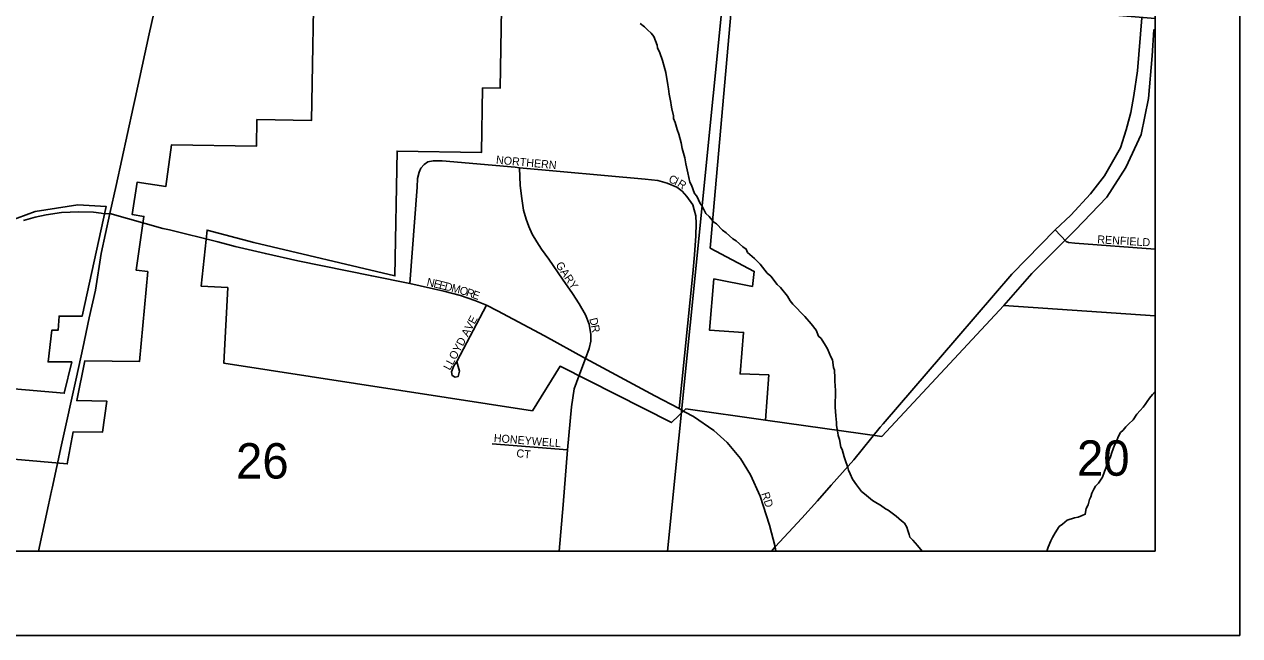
# Model space of a CAD drawing. Extents: x 8.5 to 81.5, y -1.2 to 22.4.
# Drawn here: x 54.915 to 56.353, y 14.351 to 15.074 of the extents above; entities that cross this region are included whole.
import ezdxf

# ---------------------------------------------------------------- set-up
doc = ezdxf.new("R2010")
doc.units = 0
for name, color, linetype in [('GM_X_City_Street', 7, 'Continuous'), ('GM_X_City_Street_Text', 7, 'Continuous'), ('GM_X_Corporation', 7, 'Continuous'), ('GM_X_County', 7, 'Continuous'), ('GM_X_Minor_River', 7, 'Continuous'), ('GM_X_Section', 7, 'Continuous'), ('GM_X_Section_Text', 7, 'Continuous'), ('GM_X_State_Route', 7, 'Continuous'), ('SH_Data', 7, 'Continuous')]:
    doc.layers.add(name, color=color, linetype=linetype)

msp = doc.modelspace()

# ---------------------------------------------------------------- linework, layer by layer
at = {"layer": 'GM_X_City_Street'}
for points in [[(55.3709, 14.767), (55.3793, 14.8811), (55.38, 14.8914), (55.3817, 14.8989), (55.3838, 14.9034), (55.3877, 14.9079), (55.3923, 14.9108), (55.3985, 14.9121), (55.4091, 14.9122), (55.4955, 14.9045), (55.5005, 14.904), (55.6493, 14.8906), (55.6641, 14.889), (55.6754, 14.8857), (55.6867, 14.8812), (55.693, 14.8764), (55.6985, 14.8698), (55.7056, 14.8603), (55.7072, 14.8544), (55.7092, 14.8471), (55.7097, 14.8379), (55.7093, 14.8235), (55.7075, 14.8011), (55.7057, 14.7791), (55.6894, 14.6192)], [(55.5786, 14.6784), (55.5831, 14.6901), (55.5848, 14.6988), (55.5851, 14.7068), (55.583, 14.7188), (55.5785, 14.7302), (55.5713, 14.743), (55.5633, 14.7554), (55.5513, 14.7724), (55.5353, 14.7957), (55.5265, 14.8077), (55.521, 14.8163), (55.5156, 14.8256), (55.5117, 14.8344), (55.5085, 14.8432), (55.5054, 14.854), (55.5032, 14.8677), (55.5013, 14.883), (55.5005, 14.904)], [(55.0057, 14.8501), (54.9965, 14.8513), (54.979, 14.8517), (54.9588, 14.8509), (54.9404, 14.8482), (54.9275, 14.8454), (54.9136, 14.8417)], [(55.0157, 14.85), (55.0092, 14.8496), (55.0057, 14.8501)], [(55.0827, 14.8312), (55.0784, 14.8322), (55.0157, 14.85)], [(55.16, 14.812), (55.1437, 14.8162), (55.0866, 14.8304), (55.0827, 14.8312)], [(56.1344, 14.8304), (56.1474, 14.8169), (56.15, 14.8156), (56.1575, 14.8148), (56.2527, 14.8078)], [(55.6967, 14.6151), (55.6894, 14.6192), (55.6608, 14.6343), (55.594, 14.6702), (55.5786, 14.6784), (55.5302, 14.705), (55.4747, 14.7348), (55.4614, 14.7413), (55.4476, 14.747), (55.4307, 14.7529), (55.4112, 14.7581), (55.3709, 14.767), (55.3257, 14.776), (55.2382, 14.7939), (55.1999, 14.8024), (55.164, 14.811), (55.16, 14.812)], [(55.4614, 14.7413), (55.4263, 14.6748), (55.4229, 14.6696), (55.42, 14.6628), (55.4211, 14.6582), (55.4244, 14.6562), (55.4282, 14.6572), (55.4296, 14.6633), (55.4265, 14.6744)], [(55.5477, 14.4506), (55.5524, 14.5052), (55.5574, 14.5702), (55.5621, 14.6213), (55.5653, 14.6426), (55.5706, 14.6574), (55.5786, 14.6784)], [(55.8032, 14.4558), (55.7965, 14.4813), (55.7854, 14.5156), (55.7739, 14.5406), (55.7621, 14.56), (55.7463, 14.5791), (55.7305, 14.5931), (55.7065, 14.6097), (55.6967, 14.6151)], [(55.4683, 14.5775), (55.5574, 14.5702)], [(55.8038, 14.4506), (55.8032, 14.4558)]]:
    msp.add_lwpolyline(points, dxfattribs=at)
at = {"layer": 'GM_X_Corporation'}
for p, q in [((56.2527, 15.0671), (56.2527, 20.1104)), ((56.2527, 14.729), (56.2527, 15.0671))]:
    msp.add_line(p, q, dxfattribs=at)
for points in [[(54.5101, 15.2197), (55.2579, 15.1582), (55.4802, 15.1396), (55.7533, 15.117), (55.7263, 14.809), (55.7784, 14.7813), (55.7762, 14.7636), (55.7306, 14.7725), (55.7253, 14.712), (55.7658, 14.7092), (55.7615, 14.6601), (55.7955, 14.6589), (55.7918, 14.6056), (55.9292, 14.5863), (56.0735, 14.7412), (56.1067, 14.7788), (56.1582, 14.8303), (56.1954, 14.8691), (56.2181, 14.9044), (56.236, 14.9433), (56.2448, 14.986), (56.2493, 15.0365), (56.2512, 15.0672), (56.2527, 15.0671)], [(54.5101, 15.2197), (55.2579, 15.1582), (55.2544, 14.9598), (55.1899, 14.961), (55.1893, 14.9295), (55.089, 14.9312), (55.082, 14.8818), (55.0482, 14.8871), (55.0422, 14.8488), (55.0562, 14.8465), (55.0472, 14.7827), (55.0607, 14.7811), (55.0508, 14.6747), (54.9864, 14.6758), (54.9768, 14.6286), (55.0123, 14.628), (55.0072, 14.5913), (54.9724, 14.5916), (54.9654, 14.5538), (54.8296, 14.5657)], [(55.2579, 15.1582), (55.2544, 14.9598), (55.1899, 14.961), (55.1893, 14.9295), (55.089, 14.9312), (55.082, 14.8818), (55.0482, 14.8871), (55.0422, 14.8488), (55.0562, 14.8465), (55.0472, 14.7827), (55.0607, 14.7811), (55.0508, 14.6747), (54.9864, 14.6758), (54.9768, 14.6286), (55.0123, 14.628), (55.0072, 14.5913), (54.9724, 14.5916), (54.9654, 14.5538), (54.8296, 14.5657)], [(56.2527, 14.729), (56.0735, 14.7412), (55.9292, 14.5863), (55.7918, 14.6056), (55.6975, 14.6188), (55.6804, 14.6025), (55.5486, 14.6693), (55.5158, 14.6166), (55.1507, 14.673), (55.1554, 14.7623), (55.124, 14.7639), (55.131, 14.8303), (55.1864, 14.8154), (55.3531, 14.776), (55.3557, 14.9238), (55.4555, 14.922), (55.4568, 14.9984), (55.4777, 14.998), (55.4802, 15.1396)], [(55.7533, 15.117), (55.7263, 14.809), (55.7784, 14.7813), (55.7762, 14.7636), (55.7306, 14.7725), (55.7253, 14.712), (55.7658, 14.7092), (55.7615, 14.6601), (55.7955, 14.6589), (55.7918, 14.6056), (55.6975, 14.6188), (55.6804, 14.6025), (55.5486, 14.6693), (55.5158, 14.6166), (55.1507, 14.673), (55.1554, 14.7623), (55.124, 14.7639), (55.131, 14.8303), (55.1864, 14.8154), (55.3531, 14.776), (55.3557, 14.9238), (55.4555, 14.922), (55.4568, 14.9984), (55.4777, 14.998), (55.4802, 15.1396)], [(56.2527, 15.0671), (56.2512, 15.0672), (56.2493, 15.0365), (56.2448, 14.986), (56.236, 14.9433), (56.2181, 14.9044), (56.1954, 14.8691), (56.1582, 14.8303), (56.1067, 14.7788), (56.0735, 14.7412), (56.2527, 14.729)], [(54.8469, 14.6473), (54.962, 14.6372), (54.9707, 14.6743), (54.9428, 14.6743), (54.9474, 14.712), (54.9549, 14.712), (54.9558, 14.7285), (54.9833, 14.7285), (55.0117, 14.858), (54.9779, 14.86), (54.9276, 14.8522), (54.8846, 14.8366)], [(54.8469, 14.6473), (54.962, 14.6372), (54.9707, 14.6743), (54.9428, 14.6743), (54.9474, 14.712), (54.9549, 14.712), (54.9558, 14.7285), (54.9833, 14.7285), (55.0117, 14.858), (54.9779, 14.86), (54.9276, 14.8522), (54.8846, 14.8366)], [(53.1988, 14.4506), (56.2527, 14.4506), (56.2527, 14.729)]]:
    msp.add_lwpolyline(points, dxfattribs=at)
at = {"layer": 'GM_X_County'}
msp.add_lwpolyline([(54.0879, 21.2506), (49.4527, 21.2506), (49.4527, 14.4506), (56.2527, 14.4506), (56.2527, 19.1108)], dxfattribs=at)
at = {"layer": 'GM_X_Minor_River'}
for points in [[(55.7301, 14.8401), (55.7249, 14.8463), (55.7212, 14.8498), (55.7168, 14.8586), (55.7143, 14.8617), (55.7103, 14.8702), (55.7077, 14.8736), (55.7041, 14.8832), (55.7023, 14.8871), (55.6998, 14.8981), (55.6974, 14.9085), (55.6964, 14.9157), (55.6932, 14.9268), (55.6918, 14.9333), (55.689, 14.9436), (55.6872, 14.9494), (55.6847, 14.9574), (55.6829, 14.9624), (55.6826, 14.9654), (55.6809, 14.9735), (55.6799, 14.978), (55.6795, 14.9811), (55.6775, 14.991), (55.6768, 14.9975), (55.6762, 15.0021), (55.6738, 15.0166), (55.6696, 15.0308), (55.6667, 15.0399), (55.6638, 15.0457), (55.6635, 15.0491), (55.6595, 15.0591), (55.6562, 15.063), (55.6521, 15.0672), (55.6484, 15.0707), (55.6435, 15.0746)], [(55.977, 14.4506), (55.9715, 14.4573), (55.9659, 14.4635), (55.9626, 14.467), (55.9615, 14.4701), (55.9601, 14.4751), (55.9587, 14.4789), (55.9561, 14.4835), (55.9527, 14.4863), (55.9464, 14.4921), (55.9367, 14.4992), (55.9337, 14.5007), (55.9277, 14.505), (55.924, 14.507), (55.9183, 14.5106), (55.9086, 14.5184), (55.9053, 14.5211), (55.8994, 14.5288), (55.8946, 14.5358), (55.892, 14.5419), (55.8899, 14.5465), (55.8892, 14.5496), (55.8859, 14.5584), (55.8849, 14.5619), (55.8824, 14.5707), (55.8809, 14.5737), (55.8792, 14.5825), (55.8778, 14.5875), (55.8771, 14.5906), (55.8758, 14.5993), (55.8755, 14.6028), (55.8749, 14.6104), (55.8739, 14.6207), (55.8744, 14.6405), (55.8738, 14.6515), (55.8735, 14.6557), (55.8733, 14.6645), (55.8723, 14.6679), (55.8709, 14.6767), (55.8691, 14.6802), (55.8651, 14.6898), (55.8626, 14.6936), (55.8574, 14.7021), (55.8544, 14.7048), (55.8515, 14.7117), (55.8456, 14.7194), (55.8382, 14.728), (55.8241, 14.7427), (55.8208, 14.7466), (55.8175, 14.752), (55.8093, 14.7624), (55.8056, 14.7659), (55.7979, 14.7756), (55.7938, 14.7795), (55.7852, 14.7899), (55.7786, 14.7965), (55.7704, 14.8039), (55.7689, 14.8077), (55.7648, 14.8105), (55.757, 14.8175), (55.7529, 14.8198), (55.745, 14.8269), (55.7409, 14.83), (55.7335, 14.8377), (55.7301, 14.8401)], [(56.1246, 14.4506), (56.1263, 14.4554), (56.1294, 14.4626), (56.1314, 14.4667), (56.1342, 14.472), (56.1393, 14.4795), (56.1431, 14.4825), (56.1486, 14.4873), (56.1573, 14.4898), (56.1615, 14.4909), (56.1665, 14.4927), (56.1699, 14.4941), (56.1712, 14.501), (56.1736, 14.5055), (56.1744, 14.5085), (56.1752, 14.5115), (56.1764, 14.5149), (56.1777, 14.5191), (56.1801, 14.524), (56.182, 14.5274), (56.1855, 14.5311), (56.1882, 14.5345), (56.1902, 14.5379), (56.1926, 14.5447), (56.1962, 14.5537), (56.1982, 14.5587), (56.1998, 14.562), (56.2014, 14.5673), (56.2047, 14.576), (56.2066, 14.5794), (56.2094, 14.5866), (56.2118, 14.5907), (56.2149, 14.5937), (56.218, 14.5975), (56.2215, 14.6012), (56.2265, 14.606), (56.2312, 14.6124), (56.2351, 14.6169), (56.2386, 14.621), (56.2409, 14.624), (56.2433, 14.6274), (56.246, 14.6315), (56.2495, 14.6357), (56.2526, 14.6394), (56.2527, 14.6395)]]:
    msp.add_lwpolyline(points, dxfattribs=at)
at = {"layer": 'GM_X_Section'}
msp.add_line((54.6985, 14.4506), (55.6757, 14.4506), dxfattribs=at)
for points in [[(55.6757, 14.4506), (55.7433, 15.123), (54.767, 15.2026), (54.6985, 14.4506)], [(56.2527, 15.0807), (55.7433, 15.123), (55.6757, 14.4506)], [(55.6757, 14.4506), (56.2527, 14.4506), (56.2527, 15.0807)]]:
    msp.add_lwpolyline(points, dxfattribs=at)
at = {"layer": 'GM_X_State_Route'}
for points in [[(55.0458, 14.986), (55.0622, 15.0624), (55.0754, 15.1203), (55.0879, 15.1677), (55.0886, 15.1701)], [(56.2195, 14.9531), (56.2241, 14.9694), (56.2274, 14.9894), (56.2319, 15.0186), (56.2369, 15.0813)], [(55.0157, 14.85), (55.0157, 14.85), (55.0233, 14.883), (55.0434, 14.9752), (55.0458, 14.986)], [(55.9308, 14.601), (56.0182, 14.7026), (56.0831, 14.778), (56.1344, 14.8304), (56.1529, 14.8479), (56.1763, 14.8732), (56.1928, 14.8946), (56.2118, 14.9274), (56.2183, 14.9488), (56.2195, 14.9531)], [(54.9838, 14.6906), (54.9914, 14.7264), (54.9988, 14.7594), (55.0055, 14.8027), (55.0157, 14.85)], [(54.9469, 14.5219), (54.9475, 14.525), (54.9588, 14.5761), (54.9766, 14.6563), (54.9838, 14.6906)], [(55.853, 14.5102), (55.8695, 14.5285), (55.8961, 14.5586), (55.9275, 14.5971), (55.9308, 14.601)], [(54.9315, 14.4506), (54.9432, 14.5053), (54.9469, 14.5219)], [(55.7989, 14.4506), (55.8032, 14.4558), (55.8347, 14.4897), (55.853, 14.5102)]]:
    msp.add_lwpolyline(points, dxfattribs=at)
at = {"layer": 'SH_Data'}
for p, q in [((56.3527, 21.3506), (56.3527, 14.3506)), ((56.2527, 21.2506), (56.2527, 14.4506)), ((49.4527, 14.4506), (56.2527, 14.4506)), ((49.3527, 14.3506), (56.3527, 14.3506))]:
    msp.add_line(p, q, dxfattribs=at)

# ---------------------------------------------------------------- texts
at = {"layer": 'GM_X_City_Street_Text'}
for s, rotation, p in [('NORTHERN', 354.7378, (55.4725, 14.9089)), ('C', 338.5458, (55.6762, 14.8872)), ('I', 335.0386, (55.6831, 14.8845)), ('R', 326.6198, (55.6865, 14.8829)), ('RENFIELD', 356.5821, (56.184, 14.8147)), ('GARY', 303.6885, (55.5429, 14.789)), ('N', 346.2076, (55.3901, 14.7648)), ('E', 346.2089, (55.3982, 14.7628)), ('E', 346.1824, (55.4047, 14.7612)), ('D', 346.2134, (55.4112, 14.7596)), ('M', 345.9991, (55.4193, 14.7576)), ('O', 342.7125, (55.4288, 14.7552)), ('R', 340.9815, (55.4367, 14.7528)), ('E', 340.9085, (55.4438, 14.7503)), ('LLOYD AVE', 61.8442, (55.4182, 14.6637)), ('D', 283.7235, (55.5831, 14.7253)), ('R', 280.181, (55.5851, 14.7173)), ('HONEYWELL', 355.4, (55.4699, 14.5798)), ('CT', 353.6638, (55.4965, 14.5619)), ('RD', 288.435, (55.7865, 14.5186))]:
    msp.add_text(s, height=0.00947, rotation=rotation, dxfattribs=at).set_placement(p)
at = {"layer": 'GM_X_Section_Text'}
for s, p in [('20', (56.1602, 14.5397)), ('26', (55.1652, 14.5364))]:
    msp.add_text(s, height=0.04186, rotation=0, dxfattribs=at).set_placement(p)

doc.saveas('drawing.dxf')
